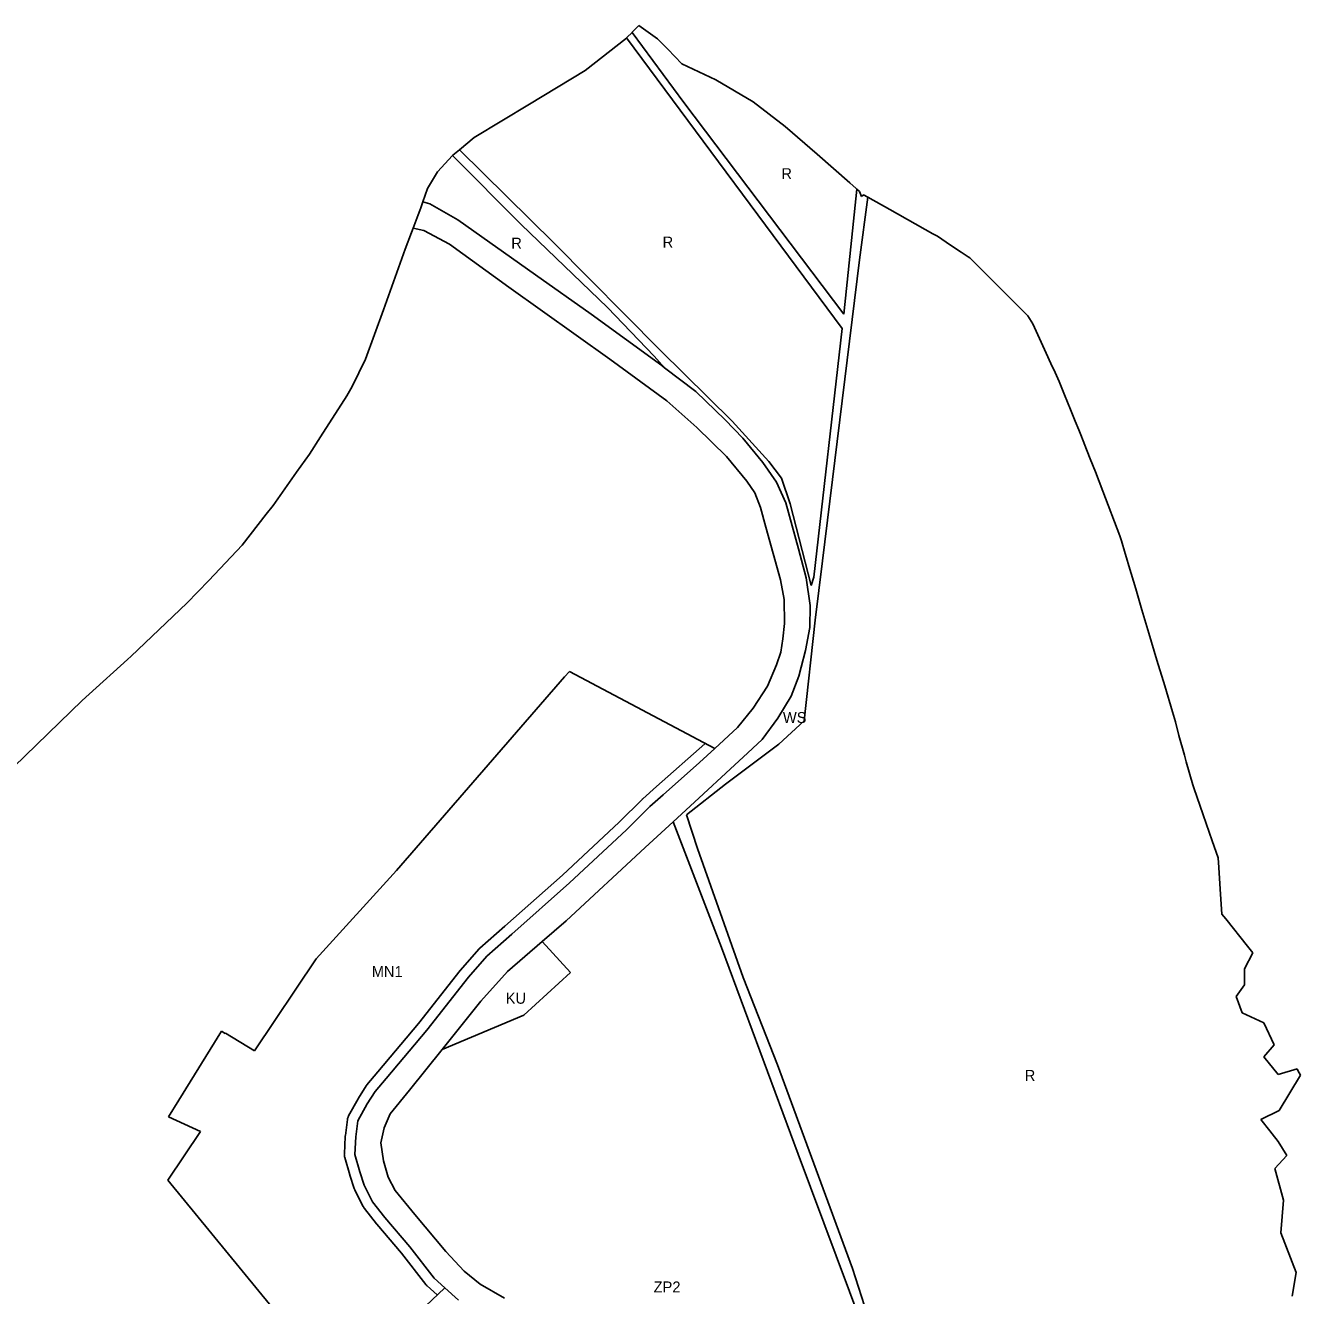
# Model space of a CAD drawing. Extents: x 7435758 to 7439981, y 5550649 to 5554049.
# Drawn here: x 7439233 to 7439840, y 5553445 to 5554049 of the extents above; entities that cross this region are included whole.
import ezdxf

# ---------------------------------------------------------------- set-up
doc = ezdxf.new("R2010")
doc.units = 0
for name, color, linetype in [('linie_rozgraniczające', 7, 'Continuous'), ('linie_zabudowy_nieprzekraczalne', 7, 'Continuous'), ('oznaczenia_przeznaczen', 7, 'Continuous')]:
    doc.layers.add(name, color=color, linetype=linetype)

msp = doc.modelspace()

# ---------------------------------------------------------------- linework, layer by layer
at = {"layer": 'linie_rozgraniczające'}
for p, q in [((7439521.96, 5554045.99), (7439525.14, 5554049.18)), ((7439525.14, 5554049.18), (7439533.95, 5554042.82)), ((7439499.63, 5554027.77), (7439519.15, 5554043.21)), ((7439519.15, 5554043.21), (7439519.29, 5554043.32)), ((7439519.29, 5554043.32), (7439519.4, 5554043.4)), ((7439519.29, 5554043.32), (7439621.8, 5553905.08)), ((7439519.4, 5554043.4), (7439521.89, 5554045.92)), ((7439521.89, 5554045.92), (7439521.96, 5554045.99)), ((7439546.56, 5554012.59), (7439521.89, 5554045.92)), ((7439533.95, 5554042.82), (7439538.84, 5554037.85)), ((7439538.84, 5554037.85), (7439545.59, 5554030.97)), ((7439545.59, 5554030.97), (7439561.7, 5554023.33)), ((7439473.16, 5554011.71), (7439499.63, 5554027.77)), ((7439561.7, 5554023.33), (7439579.49, 5554012.9)), ((7439446.82, 5553995.88), (7439473.16, 5554011.71)), ((7439622.59, 5553911.85), (7439546.56, 5554012.59)), ((7439579.49, 5554012.9), (7439594.73, 5554001.11)), ((7439594.73, 5554001.11), (7439609.96, 5553988.05)), ((7439439.82, 5553990.08), (7439446.82, 5553995.88)), ((7439429.27, 5553979.59), (7439436.46, 5553987.29)), ((7439436.46, 5553987.29), (7439436.49, 5553987.32)), ((7439436.46, 5553987.29), (7439469.19, 5553954.53)), ((7439436.49, 5553987.32), (7439436.68, 5553987.47)), ((7439436.68, 5553987.47), (7439439.73, 5553990.01)), ((7439439.73, 5553990.01), (7439439.82, 5553990.08)), ((7439484.6, 5553945.76), (7439439.82, 5553990.08)), ((7439609.96, 5553988.05), (7439617.71, 5553981.16)), ((7439617.71, 5553981.16), (7439625.47, 5553974.27)), ((7439424.63, 5553971.66), (7439429.27, 5553979.59)), ((7439625.47, 5553974.27), (7439628.49, 5553971.59)), ((7439422.39, 5553965.32), (7439424.63, 5553971.66)), ((7439628.73, 5553971.37), (7439622.59, 5553911.85)), ((7439628.49, 5553971.59), (7439628.73, 5553971.37)), ((7439628.73, 5553971.37), (7439630.05, 5553970.2)), ((7439630.05, 5553970.2), (7439630.97, 5553967.79)), ((7439630.97, 5553967.79), (7439631.91, 5553968.65)), ((7439631.91, 5553968.65), (7439634.03, 5553967.46)), ((7439420.94, 5553961.24), (7439421.38, 5553962.48)), ((7439421.38, 5553962.48), (7439422.39, 5553965.32)), ((7439425.72, 5553964.3), (7439422.39, 5553965.32)), ((7439439.05, 5553956.76), (7439425.72, 5553964.3)), ((7439630.05, 5553937.66), (7439634.03, 5553967.46)), ((7439634.03, 5553967.46), (7439644.42, 5553961.63)), ((7439644.42, 5553961.63), (7439664.95, 5553950.11)), ((7439417.73, 5553952.83), (7439420.11, 5553959.07)), ((7439420.11, 5553959.07), (7439420.94, 5553961.24)), ((7439475.93, 5553930.52), (7439439.05, 5553956.76)), ((7439413.89, 5553942.79), (7439416.9, 5553950.66)), ((7439416.9, 5553950.66), (7439417.73, 5553952.83)), ((7439417.73, 5553952.83), (7439422.85, 5553951.68)), ((7439422.85, 5553951.68), (7439435.1, 5553945.14)), ((7439469.19, 5553954.53), (7439510.12, 5553915.08)), ((7439664.95, 5553950.11), (7439667.1, 5553948.9)), ((7439435.1, 5553945.14), (7439463.28, 5553924.67)), ((7439535.22, 5553894.66), (7439484.6, 5553945.76)), ((7439667.1, 5553948.9), (7439673.33, 5553944.76)), ((7439673.33, 5553944.76), (7439678.47, 5553941.35)), ((7439403.68, 5553913.88), (7439413.89, 5553942.79)), ((7439612.46, 5553794.49), (7439630.05, 5553937.66)), ((7439678.47, 5553941.35), (7439681.73, 5553939.18)), ((7439681.73, 5553939.18), (7439682.57, 5553938.63)), ((7439682.57, 5553938.63), (7439684.76, 5553936.42)), ((7439684.76, 5553936.42), (7439691.39, 5553929.78)), ((7439502.48, 5553911.8), (7439475.93, 5553930.52)), ((7439691.39, 5553929.78), (7439694.7, 5553926.47)), ((7439694.7, 5553926.47), (7439710.07, 5553911.06)), ((7439463.28, 5553924.67), (7439511.29, 5553890.41)), ((7439395.12, 5553890.51), (7439403.68, 5553913.88)), ((7439510.12, 5553915.08), (7439532.32, 5553891.88)), ((7439536.02, 5553887.38), (7439502.48, 5553911.8)), ((7439710.07, 5553911.06), (7439712.48, 5553907.19)), ((7439712.48, 5553907.19), (7439719.66, 5553891.52)), ((7439621.8, 5553905.08), (7439608.35, 5553786.71)), ((7439388.8, 5553877.51), (7439395.12, 5553890.51)), ((7439511.29, 5553890.41), (7439538.4, 5553870.68)), ((7439532.32, 5553891.88), (7439537.31, 5553886.39)), ((7439569.55, 5553860.97), (7439535.22, 5553894.66)), ((7439719.66, 5553891.52), (7439721.74, 5553887.01)), ((7439537.31, 5553886.39), (7439536.02, 5553887.38)), ((7439537.31, 5553886.39), (7439552.15, 5553875.01)), ((7439721.74, 5553887.01), (7439722.41, 5553885.54)), ((7439722.41, 5553885.54), (7439725.04, 5553879.79)), ((7439386.28, 5553872.98), (7439388.8, 5553877.51)), ((7439725.04, 5553879.79), (7439727.58, 5553873.54)), ((7439373.74, 5553853.58), (7439386.28, 5553872.98)), ((7439538.4, 5553870.68), (7439552.72, 5553857.97)), ((7439552.15, 5553875.01), (7439566.11, 5553861.64)), ((7439727.58, 5553873.54), (7439730.41, 5553866.54)), ((7439730.41, 5553866.54), (7439732.68, 5553860.93)), ((7439566.11, 5553861.64), (7439574.54, 5553852.87)), ((7439586.98, 5553841.83), (7439569.55, 5553860.97)), ((7439732.68, 5553860.93), (7439734.35, 5553856.81)), ((7439368.39, 5553845.29), (7439373.74, 5553853.58)), ((7439552.72, 5553857.97), (7439566.82, 5553844.22)), ((7439574.54, 5553852.87), (7439584.13, 5553841.28)), ((7439734.35, 5553856.81), (7439734.96, 5553855.31)), ((7439734.96, 5553855.31), (7439736.77, 5553850.85)), ((7439736.77, 5553850.85), (7439736.95, 5553850.38)), ((7439736.95, 5553850.38), (7439739.81, 5553843.08)), ((7439362.27, 5553836.63), (7439368.39, 5553845.29)), ((7439566.82, 5553844.22), (7439576.41, 5553832.37)), ((7439584.13, 5553841.28), (7439590.5, 5553831.9)), ((7439592.97, 5553833.92), (7439586.98, 5553841.83)), ((7439739.81, 5553843.08), (7439742.22, 5553836.88)), ((7439351.15, 5553820.9), (7439362.27, 5553836.63)), ((7439742.22, 5553836.88), (7439745.8, 5553827.73)), ((7439576.41, 5553832.37), (7439580.29, 5553826.79)), ((7439590.5, 5553831.9), (7439595.06, 5553822.18)), ((7439597.01, 5553821.68), (7439592.97, 5553833.92)), ((7439580.29, 5553826.79), (7439582.91, 5553819.87)), ((7439595.06, 5553822.18), (7439601.03, 5553800.16)), ((7439745.8, 5553827.73), (7439748.36, 5553821.01)), ((7439336.46, 5553801.91), (7439347.92, 5553816.72)), ((7439347.92, 5553816.72), (7439351.15, 5553820.9)), ((7439582.91, 5553819.87), (7439585.51, 5553810.47)), ((7439607.09, 5553782.76), (7439597.01, 5553821.68)), ((7439748.36, 5553821.01), (7439751.4, 5553813.02)), ((7439585.51, 5553810.47), (7439592.51, 5553785.49)), ((7439751.4, 5553813.02), (7439753.88, 5553806.49)), ((7439753.88, 5553806.49), (7439754.64, 5553803.98)), ((7439754.64, 5553803.98), (7439756.4, 5553798.06)), ((7439320.65, 5553785.12), (7439336.46, 5553801.91)), ((7439601.03, 5553800.16), (7439604.71, 5553786.5)), ((7439756.4, 5553798.06), (7439757.05, 5553795.89)), ((7439609, 5553766.36), (7439612.46, 5553794.49)), ((7439757.05, 5553795.89), (7439758.17, 5553792.12)), ((7439758.17, 5553792.12), (7439761.41, 5553781.26)), ((7439604.71, 5553786.5), (7439606.55, 5553773.29)), ((7439608.35, 5553786.71), (7439607.09, 5553782.76)), ((7439310.14, 5553774.46), (7439320.65, 5553785.12)), ((7439592.51, 5553785.49), (7439594.19, 5553776.18)), ((7439761.41, 5553781.26), (7439764.41, 5553771.18)), ((7439283.64, 5553749.23), (7439310.14, 5553774.46)), ((7439594.19, 5553776.18), (7439594.4, 5553764.73)), ((7439606.55, 5553773.29), (7439606.45, 5553762.87)), ((7439764.41, 5553771.18), (7439767.7, 5553760.1)), ((7439594.4, 5553764.73), (7439593.65, 5553757.4)), ((7439603.68, 5553718.48), (7439609, 5553766.36)), ((7439606.45, 5553762.87), (7439604.3, 5553751.84)), ((7439593.65, 5553757.4), (7439592.6, 5553751.11)), ((7439767.7, 5553760.1), (7439771.48, 5553747.34)), ((7439592.6, 5553751.11), (7439590.51, 5553745.03)), ((7439604.3, 5553751.84), (7439602.24, 5553743.95)), ((7439263.63, 5553731.15), (7439281.86, 5553747.62)), ((7439281.86, 5553747.62), (7439283.64, 5553749.23)), ((7439590.51, 5553745.03), (7439586.36, 5553734.84)), ((7439602.24, 5553743.95), (7439601.14, 5553739.73)), ((7439771.48, 5553747.34), (7439775.22, 5553735.04)), ((7439489.79, 5553739.37), (7439409.89, 5553647.18)), ((7439492.1, 5553741.8), (7439489.79, 5553739.37)), ((7439561.24, 5553705.31), (7439492.1, 5553741.8)), ((7439601.14, 5553739.73), (7439597.49, 5553730.08)), ((7439260.4, 5553728.02), (7439263.63, 5553731.15)), ((7439586.36, 5553734.84), (7439579.49, 5553724.4)), ((7439775.22, 5553735.04), (7439778.96, 5553722.72)), ((7439227.86, 5553696.6), (7439260.4, 5553728.02)), ((7439597.49, 5553730.08), (7439591.15, 5553719.66)), ((7439579.49, 5553724.4), (7439572.05, 5553715.24)), ((7439591.15, 5553719.66), (7439583.74, 5553709.47)), ((7439778.96, 5553722.72), (7439780.27, 5553717.91)), ((7439572.05, 5553715.24), (7439561.24, 5553705.31)), ((7439591.73, 5553707.36), (7439603.68, 5553718.48)), ((7439780.27, 5553717.91), (7439782.01, 5553711.49)), ((7439566.28, 5553688.26), (7439591.73, 5553707.36)), ((7439583.74, 5553709.47), (7439574.72, 5553701.18)), ((7439782.01, 5553711.49), (7439784.56, 5553702.05)), ((7439561.24, 5553705.31), (7439553.97, 5553698.62)), ((7439574.72, 5553701.18), (7439570.69, 5553697.48)), ((7439784.56, 5553702.05), (7439785.45, 5553698.93)), ((7439553.97, 5553698.62), (7439536.7, 5553683.26)), ((7439570.69, 5553697.48), (7439551.61, 5553679.77)), ((7439785.45, 5553698.93), (7439788.59, 5553687.91)), ((7439536.7, 5553683.26), (7439530.34, 5553677.61)), ((7439547.73, 5553673.68), (7439566.28, 5553688.26)), ((7439788.59, 5553687.91), (7439789.05, 5553686.56)), ((7439789.05, 5553686.56), (7439793.52, 5553673.75)), ((7439530.34, 5553677.61), (7439519.2, 5553666.61)), ((7439551.61, 5553679.77), (7439541.46, 5553670.41)), ((7439552.99, 5553657.6), (7439547.73, 5553673.68)), ((7439793.52, 5553673.75), (7439797.82, 5553661.37)), ((7439519.2, 5553666.61), (7439492.09, 5553641.28)), ((7439528.14, 5553658.11), (7439541.46, 5553670.41)), ((7439541.46, 5553670.41), (7439564.47, 5553610.58)), ((7439797.82, 5553661.37), (7439800.63, 5553653.31)), ((7439490.48, 5553623.25), (7439528.14, 5553658.11)), ((7439574.79, 5553596.29), (7439552.99, 5553657.6)), ((7439800.63, 5553653.31), (7439800.94, 5553648.63)), ((7439409.89, 5553647.18), (7439371.55, 5553605.23)), ((7439800.94, 5553648.63), (7439801.27, 5553643.43)), ((7439492.09, 5553641.28), (7439464.69, 5553616.99)), ((7439801.27, 5553643.43), (7439801.77, 5553635.91)), ((7439801.77, 5553635.91), (7439802.39, 5553626.44)), ((7439479.18, 5553613.51), (7439490.48, 5553623.25)), ((7439802.39, 5553626.44), (7439804.22, 5553624.15)), ((7439804.22, 5553624.15), (7439814.65, 5553611.19)), ((7439464.69, 5553616.99), (7439452.74, 5553606.48)), ((7439462.55, 5553599.19), (7439479.18, 5553613.51)), ((7439492.56, 5553598.65), (7439479.18, 5553613.51)), ((7439564.47, 5553610.58), (7439600.88, 5553512.3)), ((7439814.65, 5553611.19), (7439817.1, 5553608.12)), ((7439371.55, 5553605.23), (7439342.23, 5553561.44)), ((7439452.74, 5553606.48), (7439444.03, 5553596.49)), ((7439817.1, 5553608.12), (7439813.14, 5553600.37)), ((7439449.97, 5553585.01), (7439462.55, 5553599.19)), ((7439470.39, 5553578.44), (7439492.56, 5553598.65)), ((7439813.14, 5553600.37), (7439813.13, 5553592.82)), ((7439444.03, 5553596.49), (7439424.22, 5553571.2)), ((7439591.01, 5553554.78), (7439574.79, 5553596.29)), ((7439813.13, 5553592.82), (7439809.25, 5553587.26)), ((7439809.25, 5553587.26), (7439812.03, 5553579.54)), ((7439431.48, 5553562), (7439449.97, 5553585.01)), ((7439812.03, 5553579.54), (7439822.39, 5553574.7)), ((7439431.48, 5553562), (7439470.39, 5553578.44)), ((7439822.39, 5553574.7), (7439827.21, 5553564.27)), ((7439326.58, 5553570.84), (7439306.26, 5553538.01)), ((7439328.41, 5553569.72), (7439326.58, 5553570.84)), ((7439328.43, 5553569.76), (7439328.41, 5553569.72)), ((7439342.23, 5553561.44), (7439328.43, 5553569.76)), ((7439424.22, 5553571.2), (7439404.84, 5553548.27)), ((7439416, 5553542.74), (7439431.48, 5553562)), ((7439827.21, 5553564.27), (7439822.33, 5553558.59)), ((7439822.33, 5553558.59), (7439829.2, 5553550.19)), ((7439626.65, 5553457.88), (7439591.01, 5553554.78)), ((7439829.2, 5553550.19), (7439838.14, 5553552.83)), ((7439839.8, 5553549.82), (7439829.68, 5553533.06)), ((7439838.14, 5553552.83), (7439838.56, 5553552.09)), ((7439838.56, 5553552.09), (7439839.8, 5553549.82)), ((7439404.84, 5553548.27), (7439399.62, 5553542.07)), ((7439306.26, 5553538.01), (7439301.35, 5553530.1)), ((7439399.62, 5553542.07), (7439395.95, 5553536.19)), ((7439406.82, 5553531.42), (7439416, 5553542.74)), ((7439395.95, 5553536.19), (7439391.46, 5553528.07)), ((7439403.96, 5553524.8), (7439406.82, 5553531.42)), ((7439829.68, 5553533.06), (7439820.98, 5553528.76)), ((7439301.35, 5553530.1), (7439316.55, 5553523.11)), ((7439391.46, 5553528.07), (7439390.47, 5553520.47)), ((7439820.98, 5553528.76), (7439825.2, 5553523.35)), ((7439316.55, 5553523.11), (7439301.05, 5553499.96)), ((7439390.47, 5553520.47), (7439390.02, 5553512.12)), ((7439402.43, 5553517.7), (7439403.96, 5553524.8)), ((7439825.2, 5553523.35), (7439826.34, 5553521.88)), ((7439826.34, 5553521.88), (7439829.19, 5553518.22)), ((7439403.69, 5553509.03), (7439402.43, 5553517.7)), ((7439829.19, 5553518.22), (7439833.3, 5553511.67)), ((7439390.02, 5553512.12), (7439392.44, 5553503.88)), ((7439405.83, 5553501.3), (7439403.69, 5553509.03)), ((7439600.88, 5553512.3), (7439637.66, 5553413.68)), ((7439833.3, 5553511.67), (7439827.54, 5553505.52)), ((7439392.44, 5553503.88), (7439394.52, 5553497.46)), ((7439409.21, 5553494.93), (7439405.83, 5553501.3)), ((7439827.54, 5553505.52), (7439831.65, 5553490.32)), ((7439301.05, 5553499.96), (7439384, 5553398.96)), ((7439394.52, 5553497.46), (7439398.49, 5553489.54)), ((7439418.53, 5553483.58), (7439409.21, 5553494.93)), ((7439398.49, 5553489.54), (7439404.26, 5553482.22)), ((7439831.65, 5553490.32), (7439830.52, 5553474.84)), ((7439433.31, 5553465.95), (7439418.53, 5553483.58)), ((7439404.26, 5553482.22), (7439416.16, 5553468.25)), ((7439830.52, 5553474.84), (7439837.74, 5553455.94)), ((7439416.16, 5553468.25), (7439427.7, 5553453.35)), ((7439442.02, 5553456.67), (7439433.31, 5553465.95)), ((7439427.7, 5553453.35), (7439432.82, 5553448.74)), ((7439449.57, 5553450.46), (7439442.02, 5553456.67)), ((7439636.99, 5553425.88), (7439626.65, 5553457.88)), ((7439837.74, 5553455.94), (7439835.78, 5553444.79)), ((7439411.84, 5553428.79), (7439432.82, 5553448.74)), ((7439432.82, 5553448.74), (7439439.32, 5553442.88)), ((7439461.17, 5553443.77), (7439449.57, 5553450.46))]:
    msp.add_line(p, q, dxfattribs=at)
at = {"layer": 'linie_zabudowy_nieprzekraczalne'}
for points in [[(7439533.56, 5553687.12), (7439556.41, 5553707.48)], [(7439429.19, 5553445.28), (7439424.35, 5553449.64), (7439424.31, 5553449.68), (7439424.08, 5553449.9), (7439423.86, 5553450.15), (7439423.75, 5553450.29), (7439412.27, 5553465.1), (7439400.45, 5553478.98), (7439400.42, 5553479.02), (7439400.33, 5553479.13), (7439394.57, 5553486.45), (7439394.45, 5553486.6), (7439394.27, 5553486.87), (7439394.1, 5553487.15), (7439394.02, 5553487.3), (7439390.06, 5553495.21), (7439389.99, 5553495.36), (7439389.86, 5553495.66), (7439389.77, 5553495.91), (7439387.69, 5553502.34), (7439387.67, 5553502.39), (7439387.64, 5553502.47), (7439385.23, 5553510.71), (7439385.16, 5553510.95), (7439385.1, 5553511.27), (7439385.05, 5553511.59), (7439385.03, 5553511.92), (7439385.02, 5553512.24), (7439385.03, 5553512.38), (7439385.47, 5553520.74), (7439385.49, 5553520.92), (7439385.51, 5553521.12), (7439386.5, 5553528.71), (7439386.52, 5553528.84), (7439386.58, 5553529.16), (7439386.66, 5553529.48), (7439386.77, 5553529.79), (7439386.89, 5553530.09), (7439387.03, 5553530.39), (7439387.08, 5553530.48), (7439391.57, 5553538.61), (7439391.68, 5553538.8), (7439391.71, 5553538.84), (7439395.38, 5553544.72), (7439395.53, 5553544.95), (7439395.73, 5553545.21), (7439395.79, 5553545.29), (7439401.01, 5553551.49), (7439401.02, 5553551.5), (7439420.34, 5553574.36), (7439440.1, 5553599.57), (7439440.14, 5553599.63), (7439440.26, 5553599.77), (7439448.97, 5553609.76), (7439449.07, 5553609.87), (7439449.3, 5553610.1), (7439449.44, 5553610.23), (7439461.37, 5553620.73), (7439488.73, 5553644.98), (7439515.73, 5553670.21), (7439526.83, 5553681.16), (7439526.89, 5553681.23), (7439527.02, 5553681.34), (7439533.56, 5553687.12)]]:
    msp.add_lwpolyline(points, dxfattribs=at)

# ---------------------------------------------------------------- texts
at = {"layer": 'oznaczenia_przeznaczen'}
for s, p in [('R', (7439592.9, 5553976.11)), ('R', (7439464.43, 5553943.04)), ('R', (7439536.41, 5553943.54)), ('WS', (7439593.62, 5553717.36)), ('MN1', (7439398.07, 5553596.53)), ('KU', (7439461.76, 5553583.83)), ('R', (7439708.64, 5553547.13)), ('ZP2', (7439532.15, 5553446.51))]:
    msp.add_text(s, height=5.2, dxfattribs=at).set_placement(p)

doc.saveas('drawing.dxf')
